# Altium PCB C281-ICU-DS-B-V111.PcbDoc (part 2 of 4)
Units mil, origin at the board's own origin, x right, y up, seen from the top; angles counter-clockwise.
Board outline 9370.03 x 5995.03 mil, 2 copper layers (Top Layer, Bottom Layer); 468 components, 321 nets, 1241 pads, 808 vias.
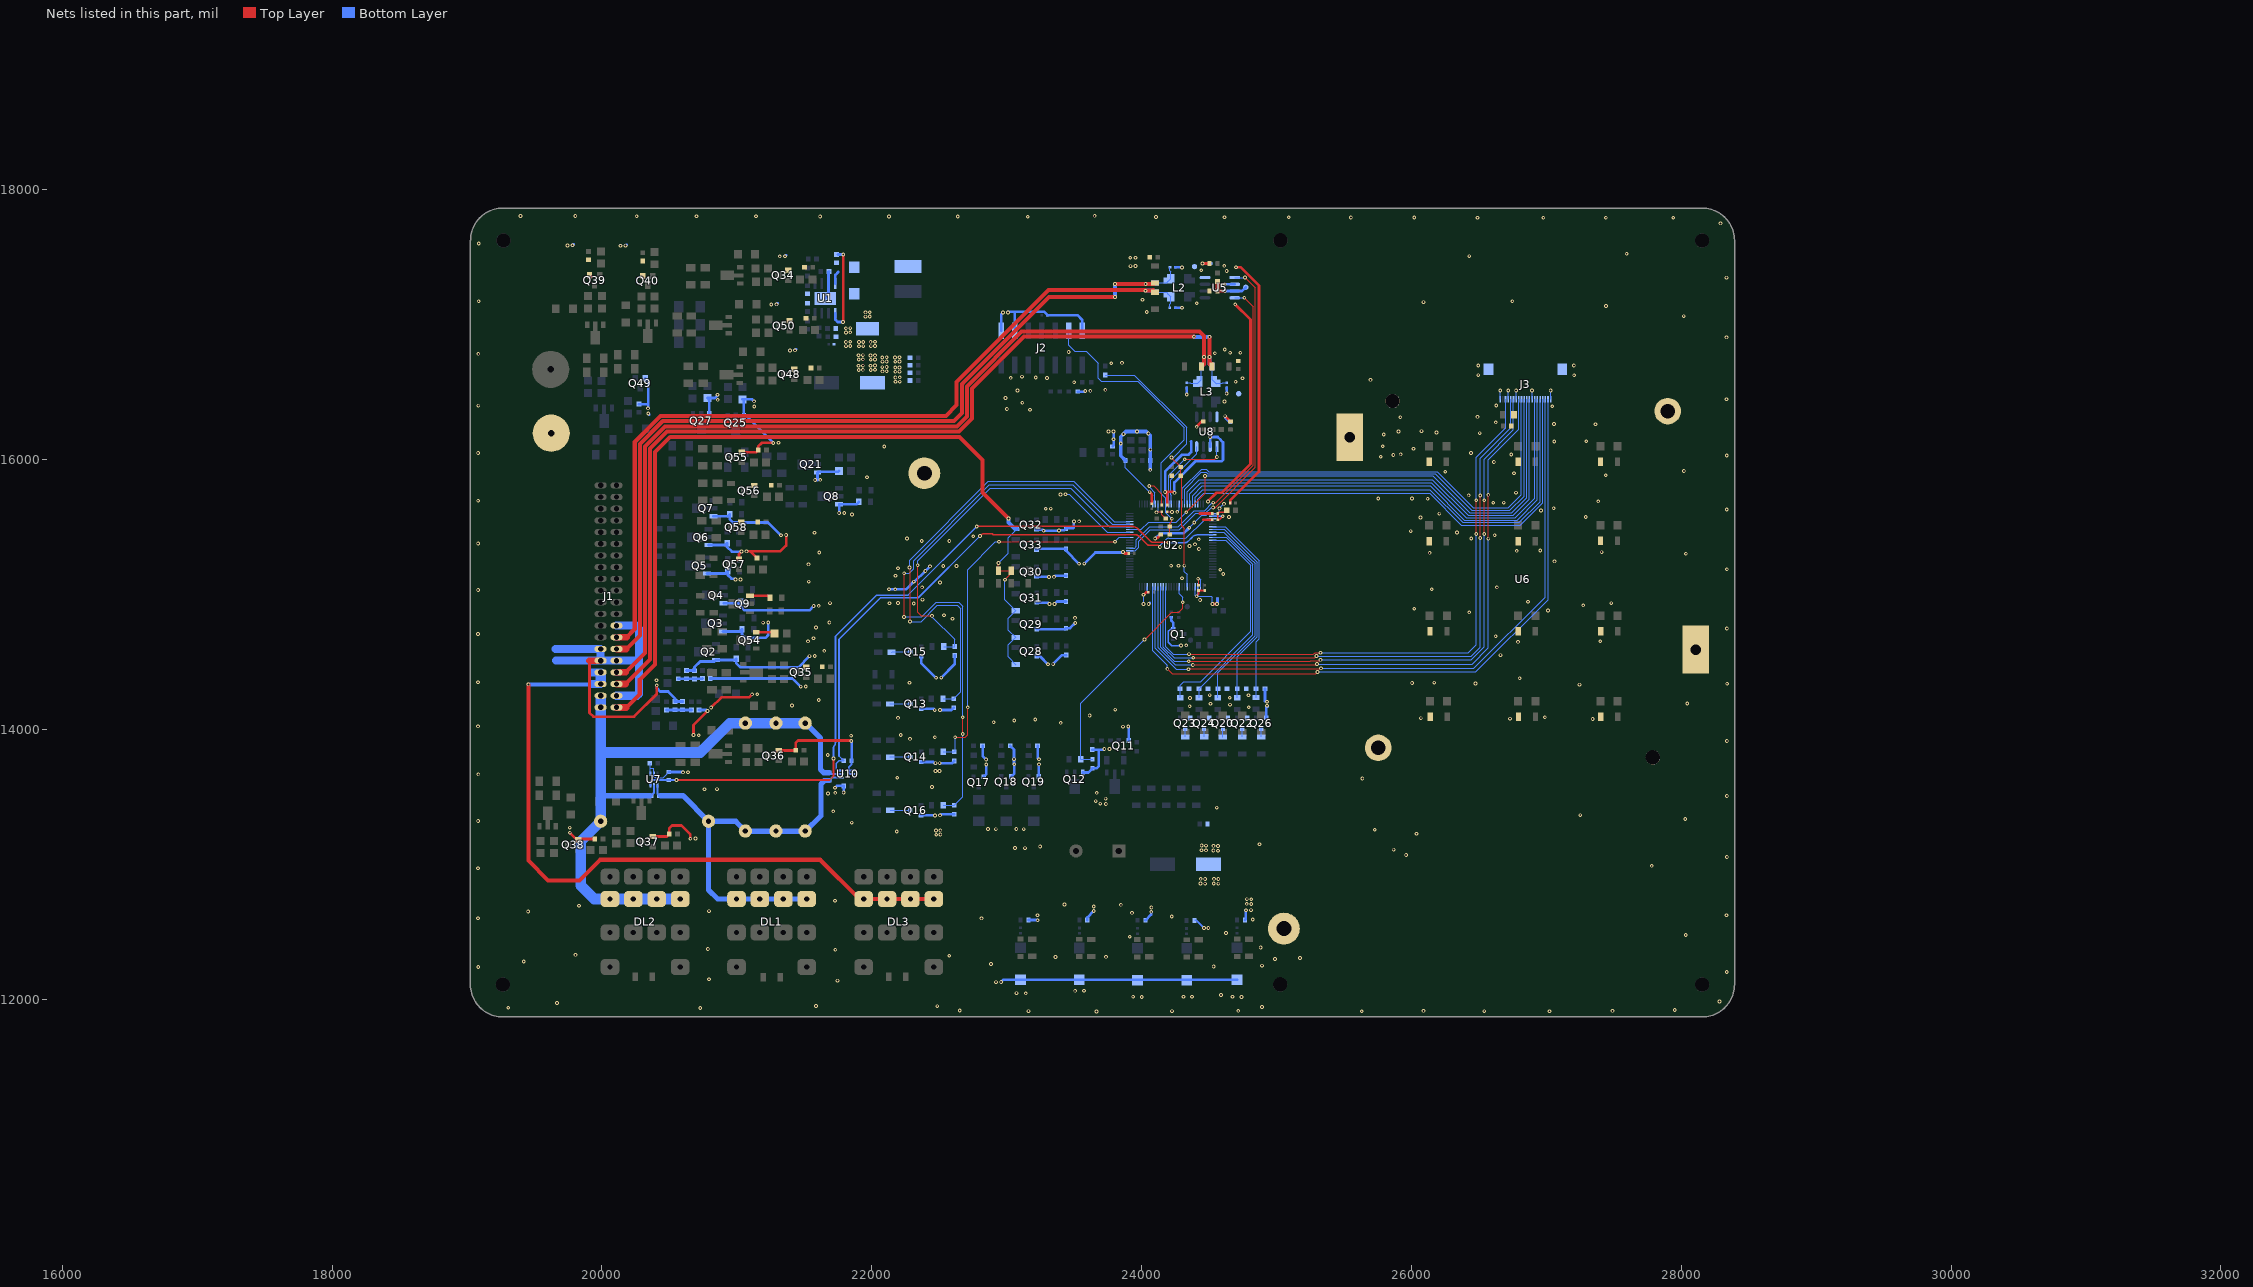
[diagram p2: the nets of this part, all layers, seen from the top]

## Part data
C9 C10 C15 C16 C57 C67: library part C103-50V-C0603, "CAP,103,50V,10%,C0603"
C11 C12 C13 C14 C20 C21 C22 C23 C25 C64: library part C104-25V-C0402-X, "CAP,104,25V,10%,C0402"
C17 C46 C50: library part C105-50V-C0603-X, "CAP,105,50V,10%,C0603"
C18 C48: library part C104-50V-C0603-X, "CAP,104,50V,10%,,C0603"
C19: library part C470UF-16V-CUT80102, "ECAP,470uF,16V,20%,φ8x10.2mm,SMD"
C24 C36 C38: library part C104-50V-C0603-X, "CAP,104,50V,10%,C0603"
C26 C27: library part C106-10V-C0402-X, "CAP,106,10V,10%,C0402"
C28 C29: library part C10pF-50V-C0603-X, "CAP,10pF,50V,5%,C0603"
C30 C31 C37 C39: library part C47pF-50V-C0402-X, "CAP,47pF,50V,10%,C0402"
C32 C33 C34 C35 C43 C44: library part C106-16V-C0603-X, "CAP,106,16V,20%,C0603"
C40 C42 C45 C47 C49 C54 C55 C56 C62 C65 C66: library part C104-50V-C0603, "CAP,104,50V,10%,C0603"
C41 C53: library part C470uF-35V-CUT100102, "ECAP,470uF,35V,20%,φ10x10.2mm,SMD"
C51: library part C102-50V-C0402-X, "CAP,102,50V,10%,C0402"
C52: library part C103-50V-C0603-X, "CAP,103,50V,10%,C0603"
C63: library part C106-16V-C0805, "CAP,106,16V,10%,C0805"
D1 D2 D3 D16 D17 D18: "Diode,Vr=1000V,If=1.0A,Vf=1.1V,DO-214AC,M7,5.26*2.79*0.9mm"
D4 D7 D10 D11 D13 D15 D19 D20 D21 D22: "Diode,IFM=300mA,VR=100V,,VRRM=100V,SOD-123,3.85*1.8*1.35mm"
D5: library part 1N4148, "Diode,If=10mA@Vf=1.0V,Wiv=75V,DO213AC,TCLL4148"
D6 D8 D9 D12 D14 D24 D25: library part 1N4148WHE3, "Diode,IFM=300mA,VR=100V,,VRRM=100V,SOD-123,2.85*1.8*1.35mm"
D26: "Diode,Vr=60V,If=3A,Vf=0.75V,DO-214AB,SS36,6.22*8.13*2.62mm"
DL1 DL2 DL3: "电磁继电器,Us=DC12V,Ui=250V,Ith=3A,GB/T14048.5-2008"
ESD1: "防静电标识"
FB3 FB4 FB5 FB7: library part 1000Ω/0.8A-AEC-Q200, "Bead,1000Ω@100MHz,25%,0.8A,1.6x0.8x0.8mm"
H1 H2 H3 H4 H7 H8: "适配M2.5*12螺钉"
H5 H6: "适配 M2.5*12 螺钉(钉帽直径6mm)"
J1: "Connector,单排针,PITCH=2.54mm,40PIN,DIP,直插,立式"
J2: library part JTAG_14PIN, "Connector,双排针,PITCH=2.54mm,14PIN,SMD"
J3: "Connector,捷康,101049-202060,PITCH=0.5mm,20PIN,H=2.5mm"
J4 J5: "Connector,4mm香蕉插头插座,H=28mm,DIP"
L2 L3: "共模电感,100uH+50/-30%@100kHz,Max DCR=2.0Ω,4.5x3.2x2.8mm"
L4: library part VLS6045EX-100M-H, "Inductor,10uH±20%,3.9AIsat),3.4A(Itemp),6.3*6*4.5mm"
LED1 LED4 LED5 LED6 LED11: library part LED-R, "LED,普通红"
LED7 LED8 LED10 LED12 LED14 LED16 LED18 LED20 LED22 LED23 LED24 LED25: library part LED-W, "LED,冷白"
LED9: library part LED-G, "LED,普通绿"
MAR1 MAR2 MAR3 MARK1: "MARK点"
Q1: "NPN,Vcbo=40V,Vceo=25V,Vebo=5V,IC=0.5A,SOT-23,3.04*1.4*1.1mm"
Q2 Q3 Q4 Q5 Q6 Q7 Q8 Q9 Q21 Q25 Q27 Q54: "NPN,Vcbo=40V,Vceo=25V,Vebo=6V,IC=1.5A,IB=0.5A,SOT-89,4.6*4.25*1.6mm"
Q10: "PNP,Vcbo=-50V,Vceo=-50V,Vebo=-5V,IC=-2A,SOT-89,4.6*2.6*1.6mm"
Q11 Q13 Q14 Q15 Q16 Q17 Q18 Q19 Q20 Q22 Q23 Q24 Q26 Q28 Q29 Q30 Q31 Q32 Q33 Q34 Q35 Q36 Q37 Q38 Q39 Q40 Q48 Q49 Q50 Q55 Q56 Q57 Q58: "NPN,Vcbo=50V,Vceo=45V,Vebo=5V,IC=500mA,SOT-23,3.04*1.4*1.1mm"
Q12: "NPN,Vcbo=50V,Vceo=50V,Vebo=5V,IC=2A,IB=0.5A,SOT-89,4.6*2.6*1.6mm"
Q41 Q42 Q43 Q44 Q45 Q46 Q47 Q51 Q52 Q53: "PNP,Vcbo=-40V,Vceo=-25V,Vebo=-5V,IC=-1.5A,SOT-89,4.6*4.25*1.6mm"
R7 R8 R13 R14 R16 R17 R26 R27 R28 R29 R30 R31 R32 R41 R42 R53 R54 R57 R60 R61 R63 R64 R68 R69 R74 R81 R84 R86 R88 R90 R92 R94 R96 R101 R121 R122 R131 R132 R135 R136 R137 R138 R218 R219 R220 R221 R222 R223 R236 R237 R263 R264: library part R30R_1206_5%, "RES,30R,1/4W,5%,R1206"
R9: library part R4K7_0603_5%_X, "RES,4K7,1/10W,5%,R0603"
R10: library part R100R_0603_1%, "RES,100R,1/10W,1%,R0603"
R11 R268: library part R0R_0603_5%_X, "RES,0R,1/10W,5%,R0603"
R12 R23: library part R10K_0603_1%_X, "RES,10K,1/10W,1%,R0603"
R15: library part R0R_0603_5%, "RES,0R,1/10W,5%,R0603"
R18 R21 R133 R141: library part NC_R0603, "NC,R0603"
R19 R25: library part R10K_0402_5%_X, "RES,10K,1/16W,5%,R0402"
R20: library part R100K_0603_1%_X, "RES,100K,1/10W,1%,R0603"
R22: library part R330R_0805_5%_X, "RES,330R,1/8W,5%,R0805"
R24: library part R1K_0402_5%_X, "RES,1K,1/16W,5%,R0402"
R33 R34: library part R100K_0402_1%_X, "RES,100K,1/16W,1%,R0402"
R35 R36 R37 R59 R62 R73 R103 R106 R107 R108 R109 R110 R111 R123 R142 R148 R150 R151 R152 R156 R158 R159 R160 R161 R164 R165 R166 R168 R170 R171 R172 R173 R176 R177 R188 R189 R196 R198 R205 R206 R207 R208 R209 R210 R224 R225 R226 R229 R230 R232 R238 R240 R244 R250 R251 R254 R255: library part R3K3_0805_5%, "RES,3K3,1/8W,5%,R0805"
R38 R39 R40 R112 R113 R114 R115 R116 R117 R118 R124 R211 R212 R213 R214 R215 R216 R217 R233 R234 R235 R239: library part R10K_0805_5%, "RES,10K,1/8W,5%,R0805"
R43 R44 R125 R126 R127 R128 R129 R130: library part R1K2_1206_1%_X, "RES,1K2,1/4W,1%,R1206"
R45 R55 R65 R71 R119: library part R1K2_1206_5%, "RES,1K2,1/4W,5%,R1206"
R46 R58 R66 R72 R120: library part R33K_0402_5%, "RES,33K,1/16W,5%,R0402"
R47 R48 R52 R78 R79 R184 R185 R186 R187 R245 R246 R257: library part R150R_1206_5%, "RES,150R,1/4W,5%,R1206"
R49 R50 R247 R248: library part R220R_1206_5%, "RES,220R,1/8W,5%,R1206"
R51 R56 R249 R258: library part R10R_1206_5%_X, "RES,10R,1/4W,5%,R1206"
R67 R70 R139 R143 R147 R149 R153 R154 R155 R157 R162 R163 R167 R169 R174 R175 R178 R179 R190 R194 R197 R199 R200 R201 R202 R203 R204 R227 R228 R231 R241 R242 R243 R252 R253 R256 R259 R260 R261 R262: library part R10K_0603_5%, "RES,10K,1/10W,5%,R0603"
R75 R104 R105: library part R1K5_1206_5%, "RES,1K5,1/4W,5%,R1206"
R76 R77 R80 R82 R83 R85 R87 R89 R91 R93 R95 R97 R98 R99 R100: library part R330R_1206_5%, "RES,330R,1/4W,5%,R1206"
R102 R144 R145 R146: library part R1R2W, "RES,1R,2W,1%,2WR"
R134: library part R1K2_1206_1%, "RES,1K2,1/4W,1%,R1206"
R140: library part NC_R1206, "NC,R1206"
R180: library part R0R_1206_5%, "RES,0R,1/4W,5%,R1206"
R181: library part R1K_1206_5%, "RES,1K,1/4W,5%,R1206"
R182: library part R2K2_1206_5%, "RES,2K2,1/4W,5%,R1206"
R183 R191 R192: library part R3K3_1206_5%, "RES,3K3,1/4W,5%,R1206"
R193: library part R200R_1206_1%, "RES,200R,1/4W,1%,R1206"
R195: library part R15K_0603_5%, "RES,15K,1/10W,5%,R0603"
R265: library part R47K_0603_1%, "RES,47K,1/10W,1%,R0603"
R266: library part R_NC_0603, "RES,R0603"
R267: library part R8.06K_0603_1%_X, "RES,8.06K,1/10W,1%,R0603"
R269: library part R100K_0603_5%_X, "RES,100K,1/10W,5%,R0603"
R270: library part R220R_0603_1%_X, "RES,220R,1/10W,1%,R0603"
SP1: "Buzzer"
SW1 SW2 SW3 SW4 SW5: library part SKPMAPE010, "按键,5.4x1.3x1.28mm"
TP13 TP14 TP15 TP16 TP17 TP18: "测试点 Φ1.0mm"
U1: "IC,JWH5123S,DCDC,ESOP-8,6x4.9x1.5mm,-40~125℃"
U2: "IC,R7F7016843AFP-C,MCU,CPU Frequency 120MHz max,Code Flash 1024KB,Data Flash 64KB,Local RAM (LRAM)96KB,Retention RAM (RRAM)32KB,Trace RAM 32KB,Renesas,LQFP100,14x14x1.7mm,-40℃ to 105℃"
U5 U8: "IC,TJA1044GT,CAN驱动芯片,Vcc=4.75~5.25V,5.0*4.0*1.75mm,SO8"
U6: "3.5 MONO_TFT,带导光罩"
U7 U10: "IC,INA214-Q1,Vcm=-0.1~26V,Vo=1~60uV,Gain=100V/V,TI,2.15x2.4x1.1mm,SC70 (6)"
Y1: library part DSX321G-8M, "Crystal,8MHz,10.0pF,SMD,3.2x2.5x1mm"

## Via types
v1: diameter 27.56, hole 13.78, Top Layer to Bottom Layer, tented both sides, 808 vias

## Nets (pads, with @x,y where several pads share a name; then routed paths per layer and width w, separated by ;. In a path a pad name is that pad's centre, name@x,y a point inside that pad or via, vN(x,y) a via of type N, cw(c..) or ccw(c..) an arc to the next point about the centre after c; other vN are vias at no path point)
A_IDDQ_KL30: C67.1 U2.59 U7.6 | length 5637.1
  Top Layer w11.81: v1(20552.72,13626) 21687.02,13626 21716,13654.98 v1(21716,13785.81) ; v1(22777.75,15505.75) 23927,15505.75 cw(c23927,15437.54) 23975.23,15485.77 24059.48,15401.52 ccw(c24093,15435.05) 24093,15387.64 24191.73,15387.64 cw(c24191.73,15378.63) v1(24198.1,15385)
  Bottom Layer w11.81: v1(21716,13785.81) 21716,13866.93 cw(c21733.07,13866.93) 21721,13879 ccw(c21696.86,13903.14) 21731,13903.14 21731,14691 22036.8,14996.8 22268.8,14996.8 v1(22777.75,15505.75) ; v1(24198.1,15385) 24320,15385 ccw(c24320,15418.8) 24343.89,15394.89 24375.59,15426.59 cw(c24417,15385.17) 24417,15443.74 U2.59@24527.09,15443.74
  Bottom Layer w15.75: U7.6@20359.41,13586.69 20359.41,13602.19 cw(c20383.22,13602.19) 20383.22,13626 20389.73,13626 20390.65,13625.08 20494.08,13625.08 C67.1@20495,13626 v1(20552.72,13626)
A_IDDQ_KL30_MCU: C57.1 U2.53 U10.6 | length 4280.3
  Top Layer w11.81: v1(22802,15435) v1@22806.46,15439.46 ; v1@22806.48,15439.48 cw(c22839,15406.92) 22839,15452.94 22883.79,15452.94 cw(c22883.79,15437.79) 22894.48,15448.52 ccw(c22905.39,15459.42) 22905.39,15444 23955,15444 cw(c23955,15410.49) 23978.69,15434.19 24039.19,15373.69 ccw(c24060.18,15394.68) 24060.18,15365 24123.23,15365 v1(24135.05,15353.19)
  Bottom Layer w7.87: v1(24135.05,15353.19) cw(c24158.84,15353.19) 24142.02,15370.02 24182.54,15410.54 cw(c24201.02,15392.03) 24201.02,15418.19 24313.37,15418.19 ccw(c24313.37,15453.97) 24338.66,15428.66 24455.99,15545.99 cw(c24494.27,15507.72) 24494.27,15561.85 U2.53@24527.09,15561.85
  Bottom Layer w11.81: U10.6@21777.56,13696.85 21747.15,13696.85 21737,13707 21737,13749.07 21757.61,13769.68 C57.1@21791.34,13769.68 21757,13804.02 21757,14670 22064.11,14977.11 22344.11,14977.11 v1(22802,15435)
AVCC5: C25.1 C26.1 FB3.1 U2.52 | length 246.2
  Top Layer w10: v1(24601.54,15581.54) 24576,15556 C25.1@24563.69,15556 C26.1@24563.69,15601.22 24574.46,15612 24619.19,15612 FB3.1@24632.04,15624.84
  Bottom Layer w11.81: U2.52@24527.09,15581.54 v1(24601.54,15581.54)
B+: C55.2 C65.2 DL2.5 DL2.6 DL2.7 DL2.8 J1.1 J1.2 R102.1 R144.1 R145.1 R146.1 U7.5 U10.5 | length 4844.8
  Bottom Layer w15.75: C65.2@20365.47,13510 20385,13529.53 U7.5@20385,13586.69 ; C55.2@21683.07,13681.1 21692.91,13671.26 U10.5@21777.56,13671.26
  Bottom Layer w39.37: 19990,13510 C65.2@20354.65,13510 ; R146.1@21509.34,14047.49 21620,13936.84 21620,13704.64 21643.54,13681.1 C55.2@21683.07,13681.1
  Bottom Layer w78.74: J1.2@19990,14231 19990,13830 ; DL2.8@20579.29,12744.37 DL2.7@20406.06,12744.37 DL2.6@20232.83,12744.37 DL2.5@20059.61,12744.37 19942.64,12744.37 19842.52,12844.49 19842.52,13172.52 R102.1@19990,13320 19990,13510 19990,13830 ; R146.1@21509.34,14047.49 21289.37,14047.49 20947.1,14047.49 20729.61,13830 19990,13830
B+~: C55.1 C65.1 DL1.5 DL1.6 DL1.7 DL1.8 R102.2 R144.2 R145.2 R146.2 U7.4 U10.4 | length 3099.3
  Bottom Layer w15.75: U7.4@20410.59,13586.69 20410.59,13523.94 C65.1@20424.53,13510 ; C55.1@21683.07,13622.05 21706.69,13645.67 U10.4@21777.56,13645.67
  Bottom Layer w39.37: C65.1@20435.35,13510 20600,13510 R102.2@20790,13320 ; DL1.8@21516.99,12744.37 DL1.7@21343.76,12744.37 DL1.6@21170.54,12744.37 DL1.5@20997.31,12744.37 20857.99,12744.37 20790,12812.37 R102.2@20790,13320 ; C55.1@21683.07,13622.05 21648.05,13622.05 21623,13597 21623,13361.15 21509.34,13247.49 21063.83,13247.49 20991.32,13320 R102.2@20790,13320
C_CANRX_OUT: U2.38 U8.4 | length 506.2
  Bottom Layer w7.87: U2.38@24220,15672.09 24220,15736.81 24216.41,15740.4 24216.41,15853.41 24407.95,16044.95 U8.4@24407.95,16097.48
C_CANTX_OUT: U2.37 U8.1 | length 703.3
  Top Layer w7.87: v1(24320,16004) 24541.55,16004 v1(24557.95,16020.4)
  Bottom Layer w7.87: U2.37@24200.31,15672.09 24200.31,15884.31 v1(24320,16004) ; v1(24557.95,16020.4) U8.1@24557.95,16097.48
CAN2_RX_MCU: U2.12 U5.4 | length 2537.4
  Top Layer w7.87: v1(24531,15682) 24549.49,15682 24828.15,15960.67 24828.15,17134.22 v1(24761.7,17200.68)
  Bottom Layer w7.87: U2.12@23912.91,15345.32 23947.31,15345.32 23959.35,15357.35 23959.35,15405.35 24059,15505 24272.24,15505 24390.53,15623.29 24466.51,15623.29 24525.22,15682 v1(24531,15682) ; U5.4@24690.09,17200.68 v1(24761.7,17200.68)
CAN2_TX_MCU: U2.11 U5.1 | length 2729.1
  Top Layer w7.87: v1(24530,15645.83) 24546.64,15645.83 24843.9,15943.1 24843.9,17273.12 v1(24766.35,17350.68)
  Bottom Layer w7.87: U2.11@23912.91,15325.63 23954.63,15325.63 23979.5,15350.5 23979.5,15395.5 24065,15481 24280.07,15481 24401.9,15602.83 24472.77,15602.83 24515.77,15645.83 v1(24530,15645.83) ; U5.1@24690.09,17350.68 v1(24766.35,17350.68)
FLMD0: J2.4 R18.1 R20.2 U2.36 | length 2181.7
  Top Layer w7.87: R20.2@24208.46,15445.75 R18.1@24208.46,15505.75 24208.46,15527.46 24224,15543 v1(24224,15563)
  Bottom Layer w7.87: J2.4@23460,16956.57 23460,16850 23505,16805 23590,16805 23680,16715 23680,16602.48 23700.25,16582.23 23970.5,16582.23 24315.03,16237.7 24315.03,16147.03 24146.18,15978.18 24146.18,15747.71 24180.63,15713.26 U2.36@24180.63,15672.09 24180.63,15606.37 v1(24224,15563)
FLMD1: R11.2 R21.1 R23.2 U2.82 | length 2051.7
  Top Layer w7.87: v1(24221,16016.4) R21.1@24290.83,15946.57 R23.2@24290.83,15881.57 24298.49,15873.91 24298.49,15510.58 24317,15492.07 v1(24317,15215)
  Bottom Layer w7.87: R11.2@23730,16628.07 23946.93,16628.07 24335.32,16239.68 24335.32,16117.32 24234.4,16016.4 v1(24221,16016.4) ; v1(24317,15215) 24317,15171 24338.11,15149.89 U2.82@24338.11,15057.91
FM_PWM_MCU: R142.1 R143.2 U2.85 | length 1720.3
  Top Layer w7.87: v1(24021.22,14667.48) 24022.29,14667.48 24225,14870.19 24274.19,14870.19 24305.12,14901.12 v1(24305.12,14944.17)
  Bottom Layer w7.87: R143.2@23636.12,13779.98 R142.1@23547.73,13779.98 23547.73,14193.99 v1(24021.22,14667.48) ; U2.85@24279.06,15057.91 24279.06,15006.37 24305.12,14980.31 v1(24305.12,14944.17)
FUEL_RES1: Q14.C R48.2 | length 152.6
  Bottom Layer w7.87: R48.2@22135.83,13795.28 22138.19,13797.64 Q14.C@22287.4,13797.64
FUEL_RES1_MCU: R62.1 R70.2 U2.16 | length 2818.8
  Top Layer w7.87: v1(22618,13943) 22618.89,13942.11 22691,13942.11 22711,13962.11 v1(22711,14165) ; v1(22943,15392) v1(23802,15392)
  Bottom Layer w7.87: R62.1@22529.94,13835.04 R70.2@22611.98,13835.04 22618,13841.06 v1(22618,13943) ; v1(22711,14165) 22711,15186.46 22916.54,15392 v1(22943,15392) ; v1(23802,15392) 23834.06,15424.06 U2.16@23912.91,15424.06
FUEL_RES2: Q13.C R51.2 | length 152.6
  Bottom Layer w7.87: R51.2@22135.83,14188.98 22138.19,14191.34 Q13.C@22287.4,14191.34
FUEL_RES2_MCU: R59.1 R67.2 U2.22 | length 3659
  Top Layer w7.87: v1(22280,15200.73) 22279,15199.73 22284.41,15194.32 22284.41,14802.2 v1(22283,14800.79)
  Bottom Layer w7.87: v1(22280,15200.73) 22280,15256 22865,15841 23498,15841 23796.83,15542.17 U2.22@23912.91,15542.17 ; v1(22283,14800.79) 22367.6,14800.79 22486.81,14920 22633,14920 22658,14895 22658,14279 R67.2@22608,14229 22607.74,14228.74 R59.1@22527.97,14228.74
FUEL_RES3: Q15.C R56.2 | length 144
  Bottom Layer w7.87: R56.2@22145.67,14572.83 22151.18,14578.35 Q15.C@22287.4,14578.35
FUEL_RES3_MCU: R73.1 R147.2 U2.20 | length 2794.7
  Top Layer w7.87: v1(22340,15218) 22340,14868 22365,14843 v1(22446,14843)
  Bottom Layer w7.87: v1(22340,15218) 22340,15252 22878,15790 23473,15790 23760.2,15502.8 U2.20@23912.91,15502.8 ; v1(22446,14843) 22446,14837.69 22615,14668.69 R147.2@22615,14615.75 R73.1@22532.61,14615.75
FUEL_RES4: Q16.C R86.2 | length 149.2
  Bottom Layer w7.87: R86.2@22135.83,13401.57 Q16.C@22285.04,13401.57
FUEL_RES4_MCU: R148.1 R149.2 U2.21 | length 4500.2
  Top Layer w7.87: v1(22239,14835) 22240,14836 v1(22240,15159) ; v1(22674,13967.7) v1(22674,14091)
  Bottom Layer w7.87: v1(22239,14835) 22369.28,14835 22477.28,14943 22644,14943 22674,14913 v1(22674,14091) ; v1(22240,15159) 22277.17,15159 22310,15191.83 22310,15253.04 22871.96,15815 23488,15815 23780.52,15522.48 U2.21@23912.91,15522.48 ; R148.1@22529.71,13438.98 R149.2@22612,13439 22674,13501 v1(22674,13967.7)
GND: C9.2 C10.2 C11.2 C12.1 C13.1 C14.1 C15.2 C16.2 C17.1 C19.2 C20.2 C21.2 C22.2 C23.2 C24.2 C25.2 C26.2 C27.2 C28.2 C29.2 C30.2 C31.2 C32.2 C33.2 C34.2 C35.2 C36.2 C37.2 C38.2 C39.2 C40.2 C41.2 C42.2 C43.1 C44.1 C45.2 C46.1 C47.2 C48.1 C49.2 C50.1 C51.1 C52.1 C53.2 C54.2 C56.2 C57.2 C62.2 C63.2 C64.2 C66.2 C67.2 D26.1 H5.1 H6.1 J1.5 J1.6 J1.22 J1.25 J1.28 J2.2 J2.12 J2.14 J3.01 J3.1 J3.02 J3.4 J3.7 J3.13 J3.20 J5.1 Q1.E Q2.E Q3.E Q4.E Q5.E Q6.E Q7.E Q8.E Q9.E Q11.E Q12.1 Q13.E Q14.E Q15.E Q16.E Q17.E Q18.E Q19.E Q20.E Q21.E Q22.E Q23.E Q24.E Q25.E Q26.E Q27.E Q28.E Q29.E Q30.E Q31.E Q32.E Q33.E Q34.E Q35.E Q36.E Q37.E Q38.E Q39.E Q40.E Q48.E Q49.E Q50.E Q54.E Q55.E Q56.E Q57.E Q58.E R12.2 R20.1 R23.1 R25.1 R33.2 R34.2 R38.1 R39.1 R40.1 R67.1 R70.1 R82.2 R83.2 R85.2 R87.2 R89.2 R91.2 R93.2 R95.2 R97.2 R98.2 R99.2 R100.2 R112.1 R113.1 R114.1 R115.1 R116.1 R117.1 R118.1 R124.1 R141.1 R143.1 R147.1 R149.1 R153.1 R154.1 R155.1 R157.1 R162.1 R163.1 R167.1 R169.1 R174.1 R175.1 R178.1 R179.1 R190.1 R194.1 R197.1 R199.1 R200.1 R201.1 R202.1 R203.1 R204.1 R227.1 R228.1 R231.1 R239.1 R243.1 R256.1 R259.1 R260.1 R261.1 R262.1 R269.2 R270.1 SW1.1 SW2.1 SW3.1 SW4.1 SW5.1 TP15.1 TP17.1 U1.0 U1.7 U2.18 U2.31 U2.41 U2.51 U2.78 U2.79 U2.97 U5.2 U5.8 U6.1 U6.2 U6.3 U6.4 U6.5 U6.6 U7.1 U7.2 U8.2 U8.8 U10.1 U10.2 | length 30608.3
  Top Layer w7.87: v1@24014,14997.32 v1(24014,14999) ; C14.1@24189.53,15615 24224,15615 v1(24226,15613)
  Top Layer w11.81: v1(24408,14988) 24421.69,15001.69 C12.1@24421.69,15030.63 C23.2@24468.94,15030.63
  Top Layer w19.68: v1(19762.13,13235) 19812.63,13184.5 19836.13,13184.5 19840.63,13189 R202.1@19946.69,13189 ; Q37.E@20377.13,13207.5 20480.87,13207.5 R201.1@20498.37,13225 20498.37,13268.37 20519,13289 20590.03,13289 20655,13224.03 v1@20655,13200.3 ; v1(20809.24,14163.57) 20885.07,14239.4 21091.4,14239.4 v1(21113,14261) ; v1(23862,15316) 23873,15305 C21.2@23905.63,15305 ; v1@24014,14997.32 24033.69,15017 C64.2@24049.31,15017 ; v1(24060,15760) 24075,15745 C22.2@24075,15675 ; v1(24100.39,15416) ccw(c24100.39,15443.52) 24119.84,15424.05 R20.1@24141.54,15445.75 ; C13.1@24189.21,15665 24189.21,15746.65 v1(24174.15,15761.71) 24235.73,15761.71 v1(24243,15754.44) ; v1(24408.64,16243.61) 24408.64,16248.09 24443.54,16282.98 C35.2@24457.48,16282.98 ; v1(24451.34,17454.68) C33.2@24504.04,17454.68 ; v1(24526,14931.31) 24557.16,14931.31 v1(24558,14930.47) ; v1(24619.14,16323.33) C34.2@24658.48,16283.98
  Top Layer w20: 19908.16,14510.84 19908.16,14123.8 19935.96,14096 20239,14096 20406,14263 v1(20406,14328) ; v1(20679,13960) 20679,14033 v1(20783,14137) ; Q57.E@21015.85,15264.1 21015.85,15301.85 v1(21034,15320) ; Q55.E@21034.99,16054.6 21141.19,16054.6 R256.1@21158.18,16071.59 21158.18,16098.75 21184.43,16125 v1(21270,16125) ; v1(21072,15321) 21100.75,15321 ; Q9.E@21097.99,14991.07 21232.22,14991.07 R124.1@21245.19,14978.11 ; Q54.E@21144.33,14720.75 21270.29,14720.75 R239.1@21279.78,14711.26 ; R261.1@21149.69,15272.07 21100.75,15321 ; Q36.E@21310.55,13845.17 21435.22,13845.17 R200.1@21437.06,13847 21437.06,13903.11 21453,13919.06 v1@21848,13919.06 ; v1(21365,15441.47) 21365,15365 21321,15321 21100.75,15321 ; 24431.46,15601.22 C26.2@24524.31,15601.22 ; 24456.77,15556 C25.2@24524.31,15556 ; v1(24492.35,15690.83) 24492.35,15693.89 24553.11,15754.65 24591.29,15754.65 24806.34,15969.7 24806.34,17039.68 v1(24694.02,17152) ; C27.2@24656.63,15679 24656.63,15697.47 24870.58,15911.42 24870.58,17291.21 24734.54,17427.25 v1(24700.31,17427.25)
  Top Layer w50: 19908.16,14510.84 J1.5@19989.89,14510.84
  Bottom Layer w7.87: C66.2@20354.33,13750 20359.41,13744.92 20359.41,13715 ; U7.1@20359.41,13673.31 20359.41,13715 ; C67.2@20495,13685.06 20454.71,13644.76 20398.81,13644.76 20397.89,13645.68 20389.89,13645.68 20385,13650.57 U7.2@20385,13673.31 20385,13712 20382,13715 20359.41,13715 ; v1(23436.17,15743.83) 23464.17,15743.83 23744.57,15463.43 U2.18@23912.91,15463.43 ; C28.2@23880,15995 23880,15940 v1(24060,15760) 24082.2,15737.8 U2.31@24082.2,15672.09 ; v1@24013,14931.64 24014,14932.64 v1(24014,14999) 24022,14999 24042.83,15019.83 U2.97@24042.83,15057.91 ; 24234,14793 24234.63,14792.37 ; v1(24264,15614) 24279.06,15629.06 U2.41@24279.06,15672.09 ; v1(24353,15496) 24444.09,15587.09 24479.3,15587.09 24493.43,15601.22 U2.51@24527.09,15601.22 24563.69,15601.22 24577,15614.54 v1(24577,15640) v1(24610,15673) ; v1@24397.17,14992.83 U2.79@24397.17,15057.91 ; U2.78@24416.85,15057.91 24416.85,14996.85 v1(24408,14988) 24515.76,14988 24522,14981.76 24522,14935.31 v1(24526,14931.31) ; J3.1@26657.99,16448.78 v1(26657.99,16512.56) ; J3.4@26717.05,16448.78 v1(26717.05,16512.56) ; J3.7@26776.1,16448.78 v1(26776.1,16512.56) ; J3.13@26894.21,16448.78 v1(26894.21,16512.56) ; J3.20@27032.01,16448.78 v1(27032.01,16512.56)
  Bottom Layer w10: Q1.E@24234.63,14745.4 24215.07,14745.4 24197.44,14727.77 24197.44,14645.67 24222.11,14621 24290.02,14621 v1(24292.39,14623.36) 24275.74,14623.36 ; C47.2@24392.41,12584.99 24406.58,12584.99 v1(24461.6,12529.97)
  Bottom Layer w14: C57.2@21850.39,13769.68 21850.39,13742.39 21828.99,13720.99 21828.99,13696.16 ; U10.2@21864.17,13671.26 21837.73,13671.26 21828.99,13680 21828.99,13696.16 ; U10.1@21864.17,13696.85 21829.67,13696.85 21828.99,13696.16
  Bottom Layer w19.68: v1@19743,17590 v1(19744.17,17588.83) ; v1(19782.17,17589.83) v1@19790.24,17597.9 ; v1@20136,17587 v1(20137.17,17585.83) ; v1(20175.17,17586.83) v1@20183.24,17594.9 ; R228.1@20274,16412.36 20340.23,16412.36 20341.83,16413.96 ; Q49.E@20321.5,16603.13 20341.83,16582.79 20341.83,16413.96 ; v1(20341.83,16381) 20341.83,16413.96 ; v1(20342.83,16343) v1@20350.9,16334.93 ; C67.2@20495,13685.06 20597.94,13685.06 v1(20600,13683) ; v1@21253.78,17152 v1(21254.95,17150.83) ; v1(21292.95,17151.83) v1@21301.02,17159.9 ; v1@21317,17509 v1(21318.17,17507.83) ; v1(21356.17,17508.83) v1@21364.24,17516.9 ; v1@21392,16811.15 v1(21393.17,16809.97) ; v1(21431.17,16810.97) v1@21439.24,16819.04 ; v1(21728,13569) 21741.68,13582.68 C56.2@21791.34,13582.68 v1(21791.34,13533.46) ; v1(21848,13916) 21850.39,13913.61 C57.2@21850.39,13769.68 ; v1(22128,15040.47) 22172.76,15040.47 v1(22173.61,15039.62) 22254.03,15039.62 v1(22311,15096.59) 22317.59,15096.59 v1(22397,15176) v1(22431,15210) ; Q16.E@22363.78,13364.17 22466.83,13364.17 v1(22468,13363) ; Q14.E@22366.14,13760.24 22454.79,13760.24 22464,13751.02 v1(22473,13751.02) ; Q13.E@22366.14,14153.94 22457.06,14153.94 v1(22467,14144) ; Q15.E@22366.14,14540.94 22366.14,14494.86 v1(22477,14384) ; v1(22503,13751.02) 22594.89,13751.02 R70.1@22611.98,13768.11 ; v1(22505,14145) 22590.93,14145 R67.1@22608,14162.07 ; v1(22506,13364) 22514.07,13372.07 R149.1@22612,13372.07 ; v1(22515,14385) 22615,14485 R147.1@22615,14548.82 ; R153.1@22821.6,13879.7 22821.6,13804.76 v1(22847.58,13778.78) ; Q17.E@22829.47,13650.58 22848.58,13669.69 v1(22848.58,13740.78) ; v1(22959,12129) 22976.08,12146.08 SW2.1@23102.29,12146.08 SW5.1@24707.37,12146.08 ; J2.14@22960,16956.57 22960,17079.31 v1(22971.97,17091.28) ; v1(23009.97,17092.28) 23015.25,17097.56 23059,17097.56 ; R154.1@23026.01,13879.7 23054.48,13851.23 v1(23054.48,13780.82) 23054.48,13743.82 v1(23055.48,13742.82) 23055.48,13672.45 Q18.E@23034.4,13651.37 ; J2.12@23060,16956.57 23060,17096.56 23059,17097.56 ; C49.2@23161.35,12588.99 23226.67,12588.99 v1(23229.36,12586.3) ; Q30.E@23220,15133.86 23310.14,15133.86 v1(23313,15131) ; Q33.E@23220,15332.2 23227.87,15340.07 R194.1@23440,15340.07 23440,15326 v1(23537,15229) ; Q32.E@23221.06,15482.38 23265.62,15482.38 v1(23274,15474) 23385.11,15474 v1(23387.5,15476.38) 23425.31,15476.38 R190.1@23440,15491.07 23491.97,15491.07 23497.83,15496.93 23497.83,15543.57 v1(23499,15542.4) ; Q31.E@23222,14941.3 23306.34,14941.3 v1(23317,14930.64) ; Q28.E@23223,14543.5 23246.5,14543.5 v1(23306,14484) ; Q29.E@23223,14743.7 23432.13,14743.7 R175.1@23440,14751.57 23469.57,14751.57 v1(23508,14790) ; R155.1@23229.28,13879.7 23229.28,13789.72 v1(23239,13780) ; Q19.E@23237.15,13651.37 23237.15,13739.15 v1(23240,13742) ; v1@23287.83,15637.65 v1(23289,15636.47) ; v1(23344,14485) 23411.17,14552.17 R174.1@23441,14552.17 ; v1(23351,15132) 23360.07,15141.07 R178.1@23440,15141.07 ; v1(23355,14931.64) 23372.53,14949.17 R179.1@23440,14949.17 ; v1@23397,15744 v1(23398.17,15742.83) ; R12.2@23526.93,16505 23576.98,16505 v1(23581.83,16509.84) ; J2.2@23560,16956.57 23560,17037.54 23527.54,17070 C11.2@23299.69,17070 23299.69,17075.37 23277.5,17097.56 23059,17097.56 ; Q12.1@23563.48,13682.33 23605.4,13682.33 R143.1@23636.12,13713.05 23664.58,13713.05 23682.83,13731.31 23682.83,13847.36 23678.58,13851.62 ; v1(23575,15230) 23657.35,15312.35 23858.35,15312.35 v1(23862,15316) ; C40.2@23597.88,12587.99 23597.88,12608.82 v1(23645.06,12656) ; v1(23619.83,16510.84) v1@23621,16509.67 ; R141.1@23633.68,13851.62 23678.58,13851.62 ; v1(23723.58,13855.42) 23719.77,13851.62 23678.58,13851.62 ; C24.2@23785,16099.06 23792.34,16106.4 v1(23792.34,16152) v1(23792.34,16209.75) ; v1(23900.58,14023) 23905.33,14018.24 Q11.E@23905.33,13918.55 ; v1@24013,14931.64 v1(24014.17,14930.47) ; C45.2@24028.24,12585.99 24071,12628.76 v1(24071,12649) ; v1(24052.17,14931.47) v1@24060.24,14939.54 ; v1(24100.39,15416) 24138.39,15454 24311,15454 v1(24353,15496) ; R25.1@24220,14831.94 24220,14807 24234,14793 ; Q1.E@24234.63,14745.4 24234.63,14792.37 ; C37.2@24248.46,17126.68 v1(24299.73,17126.68) ; C30.2@24249.46,17425.68 v1(24299.73,17425.68) ; v1(24330.39,14624.36) v1@24331.56,14623.19 ; v1(24335.03,16484) 24335.03,16532 C39.2@24335.32,16532.28 ; v1(24451.34,17454.68) R33.2@24513.88,17454.68 ; U8.2@24507.95,16097.48 v1(24507.95,16168.4) 24564.09,16168.4 24587.67,16144.82 24587.67,16144.33 24602.95,16129.05 ; v1(24558,14930.47) 24562.63,14935.1 C20.2@24562.63,14971 ; v1(24616.09,17300.68) U5.2@24690.09,17300.68 ; v1(24619.14,16323.33) 24619.14,16313.48 R34.2@24658.48,16274.14 ; v1(24630.48,16490.93) C31.2@24630.48,16531.56 ; C42.2@24766.43,12588.99 24773,12595.57 v1(24773,12660.41) ; 24914.98,14209.03 24914.98,14210.03 ; R169.1@24914.98,14302.43 24914.98,14220.03 v1(24928.57,14206.43) ; Q26.E@24923.83,14087.04 24923.83,14171.69 v1(24928.57,14176.43) v1@24933.83,14171.17
  Bottom Layer w20: v1(20406,14328) 20406,14307 20431,14282 20490.59,14282 20542,14230.59 R243.1@20542,14207.32 20542.23,14207.54 C9.2@20597.75,14207.54 ; R260.1@20626,14438.07 20683.85,14438.07 C15.2@20686,14435.92 20686,14462.45 20728.55,14505 20833.05,14505 Q2.E@20844.52,14516.47 20987.58,14516.47 R112.1@20996.39,14525.27 20996.39,14491.19 21026,14461.57 21456.3,14461.57 v1(21539,14544.28) ; C10.2@20719,14145.68 20774.31,14145.68 v1(20783,14137) ; Q5.E@20778.19,15156.94 20913.92,15156.94 R115.1@20932.51,15175.54 20932.51,15146.49 20960,15119 v1@20989,15119 ; Q6.E@20790.03,15367.57 20913.09,15367.57 R116.1@20927.51,15382 20927.51,15354.49 20963,15319 21033,15319 v1(21034,15320) ; Q27.E@20795.04,16336.65 20795.04,16443.67 R40.1@20781.63,16457.08 20836.49,16457.08 v1@20855,16475.59 ; C16.2@20803,14379.13 21411.87,14379.13 v1(21473,14318) ; Q7.E@20826.88,15581.94 20932.64,15581.94 R117.1@20947.69,15597 20947.69,15558.31 20971,15535 21230.47,15535 21326,15439.47 v1(21327,15440.47) ; Q3.E@20896.44,14727.37 21020.66,14727.37 R113.1@21037.69,14744.4 21037.69,14706.41 21064.1,14680 21212,14680 21232.5,14700.5 v1(21232.5,14793.38) ; Q4.E@20902.52,14937.23 21029.46,14937.23 21029.69,14937 21029.69,14911.31 21057,14884 21537,14884 v1(21569,14916) ; v1(21128,16433) 21113.01,16447.99 R39.1@21042.05,16447.99 21052,16438.03 Q25.E@21052,16323.33 21071.67,16323.33 v1(21270,16125) ; 21597.71,15848.71 21597.71,15851 Q21.E@21597.71,15906.11 21603.46,15911.86 21751.39,15911.86 R38.1@21756.39,15916.86 ; U1.0@21654.39,17196.11 21679.39,17221.11 U1.7@21679.39,17306.11 21679.39,17392.79 C52.1@21682.71,17396.11 ; v1(21758,15605) 21758.55,15605.55 Q8.E@21758.55,15669.83 21885.58,15669.83 R118.1@21903.75,15688 ; v1(24174.15,15761.71) 24174.15,15912.66 24298.49,16037 24346.82,16037 24367,16057.18 24367,16135.06 24366.06,16136 ; v1(24243,15754.44) 24243,15831.01 24400.73,15988.75 24593.28,15988.75 24602.95,15998.43 24602.95,16129.05 ; 24468.46,15989.44 24483.97,15989.44
  Bottom Layer w27.56: C28.2@23880,15995 23845,16030 v1(23845,16120) 23845,16170 v1(23865,16190) 23885,16210 v1(23965,16210) 24035,16210 v1(24049.76,16195.24) 24064.53,16180.47 v1(24064.53,16075) C29.2@24064.53,15995 24064,15994.47 v1(24064,15925)
  Bottom Layer w60: 19655.46,14597.46 J1.6@19989.88,14597.46 J1.5@19989.89,14510.84 ; 19658.16,14510.84 J1.5@19989.89,14510.84 ; J1.22@20108,14251 20260.23,14251 20273.16,14263.93 20273.16,14510.84 ; J1.28@20108,14770.68 20252.32,14770.68 20273.16,14749.84 20273.16,14510.84 ; J1.5@19989.89,14510.84 J1.25@20108,14510.84 20273.16,14510.84
  other v1: 23665,11910 25632,11912 27023,11912 23161,11913 24225,11913 26540,11913 24716,11915 26090,11915 27490,11915 22652,11917 27952,11922 20729,11936 19305,11938.35 24892.15,11943 22485,11950 21587,11951 19666,11973 28284,11985 24001,12017.62 24741,12018.62 23937,12019.62 24311,12019.62 24373,12019.62 24674,12019.62 24589,12032 23140.89,12044.62 23071.89,12046.62 23507.06,12063.62 23573.22,12064.62 22921,12128 21745.33,12139 20794,12149 28337,12203 19083,12240.76 24534,12244.62 24892.15,12250 22883.79,12263 19420,12281 24988,12300 25174.45,12307 23362,12313.83 23736.67,12315.57 22573.95,12324 19804,12330 21730,12368 20785,12373 24882.01,12385 23912,12464.62 28033.5,12477 24626,12492 24494.6,12528.97 24824,12592.62 19081,12601.3 22812.95,12601 24223,12614.54 23228.36,12624.3 28335,12624 23928,12641.62 19453,12651 20794,12654 24811,12661.41 24072,12681 23645.06,12689.37 19830,12694 23846,12701.08 23429,12703 24813,12707.35 24779,12708 21728,12731 24813,12742 24780,12743 24471,12858 24569,12858 24437,12858.65 24535,12858.65 24471,12892.65 24569,12892.65 24438,12893.65 24536,12893.65 19081,12972 27781,12990 28338,13055 25960.62,13071 24566,13102.32 24532,13102.96 24477.83,13105 24443.83,13105.65 25868,13110 23135.35,13121 23062,13122 23248,13133 24566,13136.96 24533,13137.96 24477.83,13139.65 24444.83,13140.65 24873.27,13150 20655,13191 20693,13192 22477.28,13220.44 22508.28,13221.66 26037,13228 22185,13245 22476,13252 22508.28,13253 25728,13258 22919.56,13262 23126,13262 22862,13262.64 23071.48,13263 19761.13,13273 21851.38,13310 19082,13322 28029,13337 27251,13366 21714,13394 24557,13421.28 23735.01,13449 23693.58,13451 23660.25,13469.75 23733.58,13488 28338,13507 21676,13526.78 21729,13531 23667,13531 20760,13558 20853,13558.41 22446,13574 25636,13636.86 22189,13643 19084,13668 20638,13684 22472,13693 22502,13693 21674,13811 23761.58,13856.42 28338,13916 22284,13931 22467.58,13943 21847,13954 20717,13958 22215.01,13960 23862.58,14022 19081,14024 23401.13,14050 22903,14054.67 23056,14067 23211.56,14075.23 27343,14079 26731,14081 26070,14085 22195,14086.8 26989,14091 23614.61,14104 23805,14147.54 24794,14166 24356,14173 21408,14178.82 24655,14185 24511,14191.34 28044,14193 21607,14220.03 24358.07,14234 24653,14235.43 24792,14254 24505,14255 21151,14262 21511,14319 27246,14333 28340,14340 26475,14341 26005.24,14345 22279,14347 26168.59,14348 19081,14351.3 20405,14366 26802,14381 21577,14545.28 26660,14552 21648.05,14583.57 26790,14650 21527,14654 27400,14655 21567.28,14676.47 26624,14692.21 19081,14708 28338,14749 21587,14756 21194.5,14792.38 21685.56,14794.5 22598,14822 23507,14828 22534.62,14847.05 26428,14869 27013,14883 26020.61,14896 21607,14917 27273,14921 22311.52,14934.32 22131,14936 21690,14937 27481.06,14937 22194,14938 26864,14947 24433.73,14961 22375.72,14963.32 19082,15035 26151,15040 22373,15054 26633,15054 22505,15091 21533,15096.59 20989,15112 21027,15113 24299.73,15121.55 22175.57,15139.76 24605,15154 24582.95,15185.17 28338,15188 22195,15196.3 22627.72,15212.35 22529.71,15213 24219,15213.94 24274,15213.94 21531.19,15224.78 27061,15246.89 28034,15303 26135,15310 21611,15313 27410,15315 26781,15324.8 26955,15327 24424.21,15339 24176.28,15352 24287,15353.65 24355.45,15360.26 24396.33,15373 19082,15380 22370.23,15397 22574.94,15398.6 24423.87,15410 22260.68,15416 26443.52,15417 22752,15433.03 26616.63,15440.04 21576,15459 26338,15461 25995,15471 24390.56,15535.35 23537,15543.4 26067,15572 24648,15575.84 27292,15576 21854,15595 26207,15600.39 21796,15606 26961,15623.29 28337,15631 23327,15637.47 27054,15641.06 26606.68,15681.57 26684.14,15682 27385,15691.45 19082,15696 26120,15711 25753.89,15712.6 26003.91,15712.91 26424,15736 26775,15756 21580,15850 21618,15851 21964,15870 27440,15885 26760,15900 26251,15911 28019,15916 26611,15984 25773,16022 28337,16031 25866,16036 26740,16039 25920,16040 19082,16050 26442,16050 26015,16082 22092,16097.48 25787,16100 21308,16126 27059,16135 27296,16137 25795,16187.35 26506,16197 26186,16202 23754.34,16208.75 25904,16209 26075,16212 27365,16263 27056,16265.64 26625,16277 25918,16315 26490,16318 23173,16371 23001,16377 21129,16395 27044,16397 19084,16401 26628.94,16401.38 23116.14,16423 24614,16432 20858,16444 28335,16448.94 22991.89,16457 20857,16482 23079.77,16514 23731,16518 23500,16575 22176.18,16578 24697,16578 22207.18,16579.22 25697,16592.39 24747,16604.58 23298,16606 23029.6,16607 23215.71,16609 22174.9,16609.56 22207.18,16610.56 23113,16616 27206,16626 26495,16627 22174.9,16652 22205.9,16653.22 22079,16655 22110,16656.22 21903,16665 21992,16665.44 21934,16666.22 22023,16666.65 22173.61,16683.56 22205.9,16684.56 22077.72,16686.56 22110,16687.56 21901.72,16696.56 21990.72,16696.99 21934,16697.56 22023,16697.99 26495,16698 27204,16698 23775,16715 23855.26,16718 22079,16727 22174,16726.88 22110,16728.22 22205,16728.1 21992,16741.31 21903,16743 22023,16742.53 21934,16744.22 22172.72,16758.44 22077.72,16758.56 22205,16759.44 22110,16759.56 21990.72,16772.87 22023,16773.87 21901.72,16774.56 21934,16775.56 19084,16785 24543.12,16789 24656,16793 24732,16793 23459,16798 24616,16818 21906,16841 21809.13,16842 21937,16842.22 21993,16842.22 21840.13,16843.22 22024,16843.44 21904.72,16872.56 21807.84,16873.56 21937,16873.56 21991.72,16873.78 21840.13,16874.56 22024,16874.78 28335,16907 21809,16943.05 21840,16944.27 21807.72,16974.61 21840,16975.61 21954,17061 21985,17062.22 28018.38,17064.61 21952.72,17092.56 21985,17093.56 24038.02,17094.98 27442,17139 24408.64,17159.68 26090,17168 19086,17175 26748,17175 24006.02,17186 28335,17350 24630.09,17399.68 24442.02,17405 23917,17435 23955,17436 24612,17437 23916.14,17496.78 23954.14,17497.78 26428,17509 27595,17527 19087,17603 28291,17752 26489,17794 26978,17794 27441,17794 27941,17794 25551,17796 26021,17796 24614,17798 25091,17798 24107,17800 23156,17801 21617,17803 22128,17803 22637,17803 20257,17805 20701,17805 21141,17805 19396,17806 19803,17806 23652,17808
HS_CAN1_H: C31.1 J1.23 L3.4 R125.2 R127.2 | length 7173.3
  Top Layer w7.87: v1(24503.48,16761.93) 24503,16761.45 24501.71,16760.16 24501.71,16738.88 24503,16737.59 24503.48,16737.11 24522.32,16718.27 R127.2@24522.32,16689.76
  Top Layer w30: 20174.61,14337.61 20356.62,14519.62 20356.62,16083.06 20481.44,16207.87 22645.87,16207.87 22744,16306 22744,16527 22743,16528 23127.25,16912.25 v1(24387,16912.25) ; R127.2@24503,16709.09 24503,16737.59 24503,16761.45 v1(24503,16911) ; v1(24503.48,16761.93) 24503.48,16737.11 24503.48,16708.61 R127.2@24522.32,16689.76
  Top Layer w50: J1.23@20108,14337.61 20174.61,14337.61
  Bottom Layer w7.87: R125.2@24522.32,16689.76 24522.32,16593.3 L3.4@24549.88,16565.75 ; L3.4@24551.7,16563.93 L3.4@24549.88,16565.75 ; C31.1@24630.48,16570.93 24601.48,16570.93 24596.3,16565.75 L3.4@24549.88,16565.75
  Bottom Layer w30: v1(24387,16912.25) 24388.25,16911 v1(24503,16911) ; v1(24503.48,16761.93) 24503.48,16708.61 R125.2@24522.32,16689.76
HS_CAN1_L: C39.1 J1.24 L3.1 R129.2 R130.2 | length 6976.6
  Top Layer w30: 20176.28,14424.23 20318.75,14566.7 20318.75,16098.75 20465.75,16245.75 22630.19,16245.75 22705.13,16320.69 22705.13,16543.69 22716.22,16554.78 ; 22716,16555 23111.13,16950.13 24429.81,16950.13 24462.48,16917.45 v1(24462.48,16761.93) 24462.48,16708.66 R129.2@24443.58,16689.76
  Top Layer w50: J1.24@20108,14424.23 20176.28,14424.23
  Bottom Layer w7.87: C39.1@24335.32,16571.65 24359.76,16571.65 24365.66,16565.75 L3.1@24416.02,16565.75 24443.58,16593.31 R130.2@24443.58,16689.76
  Bottom Layer w30: R130.2@24443.58,16689.76 24462.48,16708.66 v1(24462.48,16761.93)
HS_CAN2_H: C30.1 J1.26 L2.4 R43.2 R44.2 | length 6422.4
  Top Layer w30: 20180.45,14597.45 20280.87,14697.87 20280.87,16117.31 20450.56,16287 22609,16287 22667.25,16345.25 22667.25,16559.38 22670.46,16562.59 22670.46,16563.03 23314.36,17206.92 v1(23802.52,17206.92) ; v1(23802.52,17303.2) v1(24030,17303.2) 24092.62,17303.2 R44.2@24100.09,17310.68
  Top Layer w50: J1.26@20108,14597.45 20180.45,14597.45
  Bottom Layer w7.87: R43.2@24100.09,17310.68 24185.18,17310.68 L2.4@24195.18,17320.68 ; L2.4@24195.18,17324.11 L2.4@24195.18,17320.68 ; C30.1@24210.09,17425.68 24210.09,17399.68 24217.1,17392.67 L2.4@24217.1,17342.6 L2.4@24195.18,17320.68
  Bottom Layer w30: v1(23802.52,17206.92) v1(23802.52,17303.2) ; v1(24030,17303.2) 24092.62,17303.2 R43.2@24100.09,17310.68
HS_CAN2_L: C37.1 J1.27 L2.1 R126.2 R128.2 | length 6277.9
  Top Layer w30: 20181.65,14684.07 20243,14745.42 20243,16133 20434.87,16324.87 22549.15,16324.87 22629.38,16405.1 22629.38,16575.5 23310.55,17256.68 24024.32,17256.68 v1(24028,17253) 24080.42,17253 24084.09,17256.68 R126.2@24100.09,17240.68
  Top Layer w50: J1.27@20108,14684.07 20181.65,14684.07
  Bottom Layer w7.87: R128.2@24100.09,17240.68 24185.17,17240.68 L2.1@24195.17,17230.68 ; L2.1@24195.17,17227.25 L2.1@24195.17,17230.68 ; C37.1@24210.09,17127.68 24210.09,17152.68 24217.1,17159.68 L2.1@24217.1,17208.75 L2.1@24195.17,17230.68
  Bottom Layer w30: v1(24028,17253) 24080.42,17253 24084.09,17256.68 R128.2@24100.09,17240.68
KEY_DET: J1.21 R180.1 R181.1 R182.1 R183.1 R191.1 R195.1 | length 6527.5
  Top Layer w7.87: v1(22938.99,15234.7) R191.1@22938.99,15178 R183.1@23033,15178 23033,15157 v1(22987,15111)
  Top Layer w30: 20180.62,14164.39 20280.25,14264.02 20280.25,14369.75 20394.5,14484 20394.5,16058.47 20506.03,16170 22649.79,16170 22822,15997.79 22822,15757 v1(23014,15565)
  Top Layer w50: J1.21@20108,14164.39 20180.62,14164.39
  Bottom Layer w7.87: v1(22938.99,15234.7) 23013,15308.71 23013,15423.07 R195.1@23078,15488.07 ; v1(22987,15111) 22987,14961.17 R182.1@23067,14881.17 23012,14826.17 23012,14738.02 R181.1@23067,14683.02 23011.14,14627.16 23011.14,14538.14 R180.1@23067,14482.28
  Bottom Layer w30: v1(23014,15565) 23014,15535 23060.93,15488.07 R195.1@23078,15488.07
KL15: DL3.5 DL3.6 DL3.7 DL3.8 J1.3 J1.4 | length 5197.7
  Top Layer w30: v1(19454.58,14335) 19454.58,13029.42 19601,12883 19835,12883 19987,13035 21618,13035 21908.98,12744.02 DL3.5@21940.08,12744.02 DL3.6@22113.31,12744.02 DL3.7@22286.54,12744.02 DL3.8@22459.76,12744.02
  Bottom Layer w19.68: J1.3@19985.27,14333 J1.3@19989.89,14337.62
  Bottom Layer w30: v1(19454.58,14335) 19926.45,14335 19929.06,14337.62
  Bottom Layer w60: 19929.01,14424.23 J1.4@19979.77,14424.23 ; 19929.06,14337.62 J1.3@19989.89,14337.62
  Bottom Layer w78.74: 19989.89,14365 J1.4@19989.89,14414.11
L_SCREENA0BIT_OUT: J3.8 U2.93 | length 4942.3
  Top Layer w7.87: v1(24379.82,14479) 25293,14479 v1(25300,14486) ; v1(26570,15415) v1(26570,15740)
  Bottom Layer w7.87: U2.93@24121.57,15057.91 24121.57,14606.15 24248.73,14479 v1(24379.82,14479) ; v1(25300,14486) 26451,14486 26570,14605 v1(26570,15415) ; v1(26570,15740) 26570,16000 26795.79,16225.79 J3.8@26795.79,16448.78
L_SCREEND0BIT_OUT: J3.9 U2.42 | length 3555.2
  Bottom Layer w7.87: U2.42@24298.74,15672.09 24298.74,15709.31 24302.68,15713.24 24302.68,15786.95 24446.56,15930.83 24479.24,15930.83 24498.57,15911.5 26189.5,15911.5 26456.83,15644.17 26718.17,15644.17 26815.47,15741.47 J3.9@26815.47,16448.78
L_SCREEND1BIT_OUT: J3.10 U2.43 | length 3554.1
  Bottom Layer w7.87: U2.43@24318.43,15672.09 24318.43,15780.43 24443.59,15905.59 24480.6,15905.59 24490.44,15895.75 26176.25,15895.75 26446.19,15625.81 26729.95,15625.81 26835.16,15731.02 J3.10@26835.16,16448.78
L_SCREEND2BIT_OUT: J3.11 U2.19 | length 4071.6
  Top Layer w7.87: v1(24331,15611) 24470,15750 v1(24470,15880)
  Bottom Layer w7.87: U2.19@23912.91,15483.11 23997.82,15483.11 24051.71,15537 24257,15537 v1(24331,15611) ; v1(24470,15880) 26159,15880 26432,15607 26742.19,15607 26854.84,15719.65 J3.11@26854.84,16448.78 J3.11@26855,16448.62
L_SCREEND3BIT_OUT: J3.12 U2.44 | length 3565.1
  Bottom Layer w7.87: U2.44@24338.11,15672.09 24338.11,15763.11 24428.35,15853.35 26155.33,15853.35 26420.23,15588.45 26755.45,15588.45 26874.53,15707.53 J3.12@26874.53,16448.78
L_SCREEND4BIT_OUT: J3.14 U2.45 | length 3567.2
  Bottom Layer w7.87: U2.45@24357.8,15672.09 24357.8,15748.8 24439,15830 26147,15830 26406,15571 26770,15571 26913.9,15714.9 J3.14@26913.9,16448.78
L_SCREEND5BIT_OUT: J3.15 U2.46 | length 3561.9
  Bottom Layer w7.87: U2.46@24377.48,15672.09 24377.48,15734.48 24450.09,15807.09 26138.91,15807.09 26392.94,15553.06 26784.06,15553.06 26933.58,15702.58 J3.15@26933.58,16448.78
L_SCREEND6BIT_OUT: J3.16 U2.47 | length 3551.6
  Bottom Layer w7.87: U2.47@24397.17,15672.09 24397.17,15721.17 24453.56,15777.56 26136.44,15777.56 26378.65,15535.35 26798.51,15535.35 26953.27,15690.11 J3.16@26953.27,16448.78
L_SCREEND7BIT_OUT: J3.17 U2.48 | length 3543.2
  Bottom Layer w7.87: U2.48@24416.85,15672.09 24416.85,15707.85 24459.31,15750.31 26135.69,15750.31 26370.53,15515.47 26807.57,15515.47 26972.95,15680.86 J3.17@26972.95,16448.78
L_SCREENTEBIT_OUT: J3.19 U2.95 | length 5204.5
  Top Layer w7.87: v1(24190.91,14450) 24228.91,14412 25289,14412 v1(25304,14427)
  Bottom Layer w7.87: U2.95@24082.2,15057.91 24082.2,14584.8 24190.91,14476.09 v1(24190.91,14450) ; v1(25304,14427) 26477,14427 27012.32,14962.32 J3.19@27012.32,16448.78
L_SCREENXCSBIT_OUT: J3.3 U2.90 | length 4705.1
  Top Layer w7.87: v1(24351,14559) 25273.81,14559 25285.4,14570.59 25325.41,14570.59 v1(25326,14570) ; v1(26480,15450) v1(26480,15700)
  Bottom Layer w7.87: U2.90@24180.63,15057.91 24180.63,14614.37 24236,14559 v1(24351,14559) ; v1(25326,14570) 26421,14570 26480,14629 v1(26480,15450) ; v1(26480,15700) 26480,16020 26697.36,16237.36 J3.3@26697.36,16448.78
L_SCREENXRDBIT_OUT: J3.6 U2.92 | length 4858.4
  Top Layer w7.87: v1(24349,14507) 24349.23,14506.77 25250.58,14506.77 25255.4,14511.59 25320.59,14511.59 v1(25326,14517) ; v1(26540,15450) v1(26540,15700)
  Bottom Layer w7.87: U2.92@24141.26,15057.91 24141.26,14608.74 24243,14507 v1(24349,14507) ; v1(25326,14517) 26442,14517 26540,14615 v1(26540,15450) ; v1(26540,15700) 26540,16005 26756.42,16221.42 J3.6@26756.42,16448.78
L_SCREENXRESBIT_OUT: J3.18 U2.94 | length 5105
  Top Layer w7.87: v1(24348,14447) 24353.59,14452.59 25333.77,14452.59 v1@25335.18,14454
  Bottom Layer w7.87: U2.94@24101.89,15057.91 24101.89,14603.57 24258.46,14447 v1(24348,14447) ; v1(25329,14454) 26462,14454 26463,14453 26992.64,14982.64 J3.18@26992.64,16448.78
L_SCREENXWRBIT_OUT: J3.5 U2.91 | length 4793.6
  Top Layer w7.87: v1(24382.91,14532.36) 25283.36,14532.36 v1(25296,14545) ; v1(26510,15420) v1(26510,15735)
  Bottom Layer w7.87: U2.91@24160.94,15057.91 24160.94,14611.78 24240.36,14532.36 24338.17,14532.36 24338.4,14532.59 24382.68,14532.59 v1(24382.91,14532.36) ; v1(25296,14545) 25296.59,14544.41 26444.41,14544.41 26510,14610 v1(26510,15420) ; v1(26510,15735) 26510,16010 26736.73,16236.73 J3.5@26736.73,16448.78
LED1: Q23.C R76.2 | length 62.3
  Bottom Layer w7.87: R76.2@24322.73,13945.54 Q23.C@24322.73,14007.86
LED1_MCU: R160.1 R163.2 U2.61 | length 1633.1
  Bottom Layer w7.87: R160.1@24285.33,14235.24 R163.2@24285.33,14302.43 24285.33,14328.83 24311.93,14355.43 24437.43,14355.43 24809,14727 24809,15219.37 24624,15404.37 U2.61@24527.09,15404.37
LED2: Q24.C R77.2 | length 61.6
  Bottom Layer w7.87: R77.2@24463.2,13946.25 Q24.C@24463.2,14007.86
LED2_MCU: R164.1 R167.2 U2.60 | length 1535.6
  Bottom Layer w7.87: R164.1@24425.8,14235.24 R167.2@24425.8,14302.43 24824.75,14701.38 24824.75,15225.89 24626.59,15424.06 U2.60@24527.09,15424.06
LED3: Q20.C R78.2 | length 62.9
  Bottom Layer w7.87: R78.2@24603.05,13944.97 Q20.C@24603.05,14007.86
LED3_MCU: R156.1 R157.2 U2.58 | length 1520.3
  Bottom Layer w7.87: U2.58@24527.09,15463.43 24609.57,15463.43 24806.93,15266.07 24806.93,15265.98 24840.5,15232.42 24840.5,14694.86 24565.65,14420 R157.2@24565.65,14302.43 24565.65,14235.43 R156.1@24565.45,14235.24
LED4: Q22.C R79.2 | length 62.3
  Bottom Layer w7.87: R79.2@24745.84,13945.54 Q22.C@24745.84,14007.86
LED4_MCU: R159.1 R162.2 U2.57 | length 1495.3
  Bottom Layer w7.87: U2.57@24527.09,15483.11 24612.16,15483.11 24856.24,15239.03 24856.24,14688.33 24708.44,14540.53 R162.2@24708.44,14302.43 R159.1@24708.44,14235.24
LED5: Q26.C R80.2 | length 62.8
  Bottom Layer w7.87: R80.2@24886.43,13945.54 Q26.C@24886.43,14008.3
LED5_MCU: R166.1 R169.2 U2.56 | length 1472.8
  Bottom Layer w7.87: U2.56@24527.09,15502.8 24620.2,15502.8 24871.99,15251.01 24871.99,14674.95 24848.05,14651.01 R169.2@24848.05,14302.43 R166.1@24848.05,14237.3
NetC9_1: C9.1 R241.1 R242.2 R243.2 | length 184
  Bottom Layer w20: R241.1@20479,14145.68 R242.2@20663,14145.68
NetC12_2: C12.2 U2.77 | length 122.2
  Top Layer w7.87: v1(24419.24,15118.08) 24419.24,15113.14 24421.69,15110.69 C12.2@24421.69,15070
  Bottom Layer w7.87: v1(24419.24,15118.08) 24429.08,15118.08 24436.54,15110.63 U2.77@24436.54,15057.91
NetC13_2: C13.2 U2.32 | length 351.7
  Top Layer w7.87: v1(24056.29,15806) 24089,15806 24149.84,15745.16 C13.2@24149.84,15665
  Bottom Layer w7.87: v1(24056.29,15806) 24056.29,15799.9 24098.94,15757.25 24098.94,15675.04 U2.32@24101.89,15672.09
NetC14_2: C14.2 R15.2 U2.33 | length 170.8
  Top Layer w7.87: v1(24110,15610) 24115,15615 C14.2@24150.16,15615 24150.16,15593.31 R15.2@24178.46,15565
  Bottom Layer w7.87: v1(24110,15610) 24121.57,15621.57 U2.33@24121.57,15672.09
NetC15_1: C15.1 R252.1 R253.2 R260.2 | length 179.1
  Bottom Layer w20: R252.1@20566,14377.29 20743.64,14377.29 R253.2@20744.64,14378.29
NetC18_1: C18.1 D26.2 L4.1 U1.8 | length 94.1
  Bottom Layer w20: U1.8@21729.39,17306.11 21729.39,17369.11 21751.39,17391.11
NetC18_2: C18.2 U1.1 | length 651.7
  Top Layer w20: v1(21786.39,17021.11) 21788.39,17023.11 v1(21788.39,17521.48)
  Bottom Layer w20: U1.1@21729.39,17086.11 21729.39,17039.11 21747.39,17021.11 v1(21786.39,17021.11) ; C18.2@21749.39,17521.43 21749.45,17521.48 v1(21788.39,17521.48)
NetC32_1: C32.1 FB4.1 TP16.1 U5.3 | length 290.8
  Top Layer w19.68: C32.1@24563.09,17250.68 v1(24616.09,17250.68)
  Top Layer w31.5: C32.1@24563.09,17250.68 FB4.1@24563.09,17320.68
  Bottom Layer w19.68: v1(24616.09,17250.68) 24621.66,17250.68 24621.91,17250.93 24639.85,17250.93 24640.1,17250.68 U5.3@24690.09,17250.68 24744.1,17250.68 TP16.1@24772.09,17278.68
